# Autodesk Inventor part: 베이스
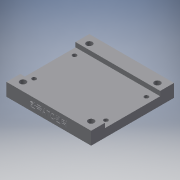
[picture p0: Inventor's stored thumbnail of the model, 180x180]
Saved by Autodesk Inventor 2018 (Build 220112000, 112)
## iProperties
Created: 2020-03
Part Number: 베이스
Material: 알루미늄 6061
Document SubType Name: Modeling
Designer: mduedu
Density: 2.71 g/cm^3
Mass: 231.03 g
Surface Area: 235.596 cm^2
Volume: 85.2508 cm^3
Appearance: 기본값
Author: mduedu
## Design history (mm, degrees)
sketch "스케치1"
  geometry: L1 (0, 45)-(-92, 45); L2 (-92, 45)-(-92, -45); L3 (-92, -45)-(0, -45); L4 (0, -45)-(0, 45); 2 further points
  constraints: 8 end point, 2 parallel, 1 coincident, 1 horizontal, 1 midpoint, 1 perpendicular
  dimensions: "d0" = 92 distance of L1.start L1.end; "d2" = 90 distance of L1.end L2.end
extrude "돌출1" new body sketch "스케치1" distance "d3" = 14; taper "d4" = 0 deg
sketch "스케치2"
  geometry: L1 (40, 0)-(50, 0); L2 (50, 0)-(50, 3); L3 (50, 3)-(40, 3); L4 (40, 3)-(40, 0); L5 (15, 14)-(75, 14); L6 (75, 14)-(75, 9); L7 (75, 9)-(15, 9); L8 (15, 9)-(15, 14); L9 (0, 0)-(90, 0) reference; L10 (0, 14)-(90, 14) reference; 3 further points
  constraints: 16 end point, 4 parallel, 2 collinear, 2 horizontal, 2 midpoint, 2 perpendicular, 1 vertical alignment
  dimensions: "d5" = 60 distance of L5.start L5.end; "d7" = 5 distance of L5.end L6.end; "d8" = 10 distance of L1.start L1.end; "d9" = 3 distance of L1.end L2.end
extrude "돌출2" cut sketch "스케치2" extent not by distance; stored distance "d10" = 14; taper "d11" = 0 deg
sketch "스케치3"
  geometry: L1 (9, 36)-(83, 36); L2 (83, 36)-(83, -36); L3 (83, -36)-(9, -36); L4 (9, -36)-(9, 36); L5 (92, 30)-(92, -30) reference; 2 further points
  constraints: 8 end point, 2 parallel, 1 horizontal, 1 horizontal alignment, 1 midpoint, 1 perpendicular
  dimensions: "d12" = 72 distance of L1.end L2.end; "d14" = 74 distance of L1.start L1.end; "d15" = 9 distance between parallel lines of L5 L2
hole "구멍1" sketch "스케치3" at (9, -36), (83, -36), (83, 36), (9, 36) diameter "d16" = 6.6; stored, may be unused: countersink angle "d20" = 90 deg, drill point angle "d22" = 118 deg; dims "d17" = 6, "d18" = 4, "d19" = 2, "d21" = 8
sketch "스케치4"
  geometry: L1 (7, 22)-(85, 22); L2 (85, 22)-(85, -22); L3 (85, -22)-(7, -22); L4 (7, -22)-(7, 22); L5 (0, -45)-(0, 45) reference; L6 (92, 45)-(92, -45) reference; 5 further points
  constraints: 8 end point, 2 parallel, 1 horizontal, 1 horizontal alignment, 1 midpoint, 1 perpendicular
  dimensions: "d26" = 7 distance between parallel lines of L4 L5; "d27" = 7 distance between parallel lines of L6 L2; "d28" = 44 distance of L1.end L2.end
hole "구멍2" sketch "스케치4" at (7, 22), (85, 22), (85, -22), (7, -22) diameter "d29" = 4.5; stored, may be unused: countersink angle "d33" = 90 deg, drill point angle "d35" = 118 deg; dims "d30" = 6, "d31" = 8, "d32" = 4.4, "d34" = 8
sketch "스케치5"
  geometry: L1 (0, 0)-(92, 0) reference; 5 further points
  constraints: 3 coincident, 1 midpoint, 1 vertical alignment, 1 other
  dimensions: "d36" = 7 distance of point (46, 7) point (46, 0)
feature "엠보싱1" sketch "스케치5" dims "d37" = 0.5, "d38" = 0
node "작업 평면1"
node "솔리드1"
